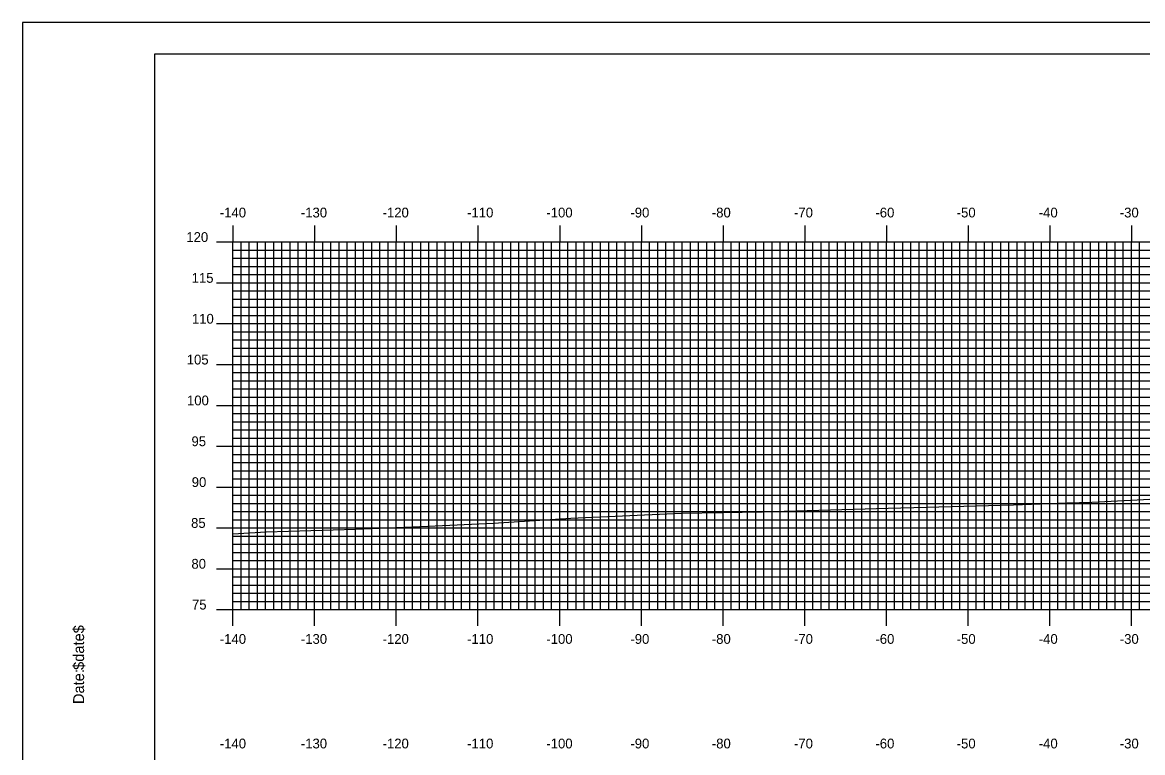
# Model space of a CAD drawing. Extents: x 485 to 829, y -1658 to -1438.
# Drawn here: x 485.3 to 622.5, y -1527.1 to -1437.7 of the extents above; entities that cross this region are included whole.
import ezdxf

# ---------------------------------------------------------------- set-up
doc = ezdxf.new("R2010")
doc.units = 0
for name, color, linetype in [('BORDER', 7, 'Continuous'), ('H_V ANNOTATION', 7, 'Continuous'), ('MAJOR', 7, 'Continuous'), ('MINOR', 7, 'Continuous'), ('PLOT BOUNDARY', 7, 'Continuous'), ('S_Roadway_Centerline', 7, 'Continuous')]:
    doc.layers.add(name, color=color, linetype=linetype)

msp = doc.modelspace()

# ---------------------------------------------------------------- linework, layer by layer
at = {"layer": 'BORDER'}
msp.add_lwpolyline([(501.53, -1651.6), (821.53, -1651.6), (821.53, -1441.6), (501.53, -1441.6)], close=True, dxfattribs=at)
at = {"layer": 'MAJOR'}
for p, q in [((511.13, -1462.6), (511.13, -1464.6)), ((521.13, -1462.6), (521.13, -1464.6)), ((531.13, -1462.6), (531.13, -1464.6)), ((541.13, -1462.6), (541.13, -1464.6)), ((551.13, -1462.6), (551.13, -1464.6)), ((561.13, -1462.6), (561.13, -1464.6)), ((571.13, -1462.6), (571.13, -1464.6)), ((581.13, -1462.6), (581.13, -1464.6)), ((591.13, -1462.6), (591.13, -1464.6)), ((601.13, -1462.6), (601.13, -1464.6)), ((611.13, -1462.6), (611.13, -1464.6)), ((621.13, -1462.6), (621.13, -1464.6)), ((509.13, -1464.6), (511.13, -1464.6)), ((511.13, -1464.6), (791.13, -1464.6)), ((511.13, -1509.6), (511.13, -1464.6)), ((511.13, -1509.6), (511.13, -1464.6)), ((511.13, -1464.6), (791.13, -1464.6)), ((521.13, -1509.6), (521.13, -1464.6)), ((531.13, -1509.6), (531.13, -1464.6)), ((541.13, -1509.6), (541.13, -1464.6)), ((551.13, -1509.6), (551.13, -1464.6)), ((561.13, -1509.6), (561.13, -1464.6)), ((571.13, -1509.6), (571.13, -1464.6)), ((581.13, -1509.6), (581.13, -1464.6)), ((591.13, -1509.6), (591.13, -1464.6)), ((601.13, -1509.6), (601.13, -1464.6)), ((611.13, -1509.6), (611.13, -1464.6)), ((621.13, -1509.6), (621.13, -1464.6)), ((509.13, -1469.6), (511.13, -1469.6)), ((511.13, -1469.6), (791.13, -1469.6)), ((509.13, -1474.6), (511.13, -1474.6)), ((511.13, -1474.6), (791.13, -1474.6)), ((509.13, -1479.6), (511.13, -1479.6)), ((511.13, -1479.6), (791.13, -1479.6)), ((509.13, -1484.6), (511.13, -1484.6)), ((511.13, -1484.6), (791.13, -1484.6)), ((509.13, -1489.6), (511.13, -1489.6)), ((511.13, -1489.6), (791.13, -1489.6)), ((509.13, -1494.6), (511.13, -1494.6)), ((511.13, -1494.6), (791.13, -1494.6)), ((509.13, -1499.6), (511.13, -1499.6)), ((511.13, -1499.6), (791.13, -1499.6)), ((509.13, -1504.6), (511.13, -1504.6)), ((511.13, -1504.6), (791.13, -1504.6)), ((509.13, -1509.6), (511.13, -1509.6)), ((511.13, -1509.6), (791.13, -1509.6)), ((511.13, -1509.6), (791.13, -1509.6)), ((511.13, -1511.61), (511.13, -1509.6)), ((521.13, -1511.61), (521.13, -1509.6)), ((531.13, -1511.61), (531.13, -1509.6)), ((541.13, -1511.61), (541.13, -1509.6)), ((551.13, -1511.61), (551.13, -1509.6)), ((561.13, -1511.61), (561.13, -1509.6)), ((571.13, -1511.61), (571.13, -1509.6)), ((581.13, -1511.61), (581.13, -1509.6)), ((591.13, -1511.61), (591.13, -1509.6)), ((601.13, -1511.61), (601.13, -1509.6)), ((611.13, -1511.61), (611.13, -1509.6)), ((621.13, -1511.61), (621.13, -1509.6))]:
    msp.add_line(p, q, dxfattribs=at)
at = {"layer": 'MINOR'}
for p, q in [((512.13, -1509.6), (512.13, -1464.6)), ((513.13, -1509.6), (513.13, -1464.6)), ((514.13, -1509.6), (514.13, -1464.6)), ((515.13, -1509.6), (515.13, -1464.6)), ((516.13, -1509.6), (516.13, -1464.6)), ((517.13, -1509.6), (517.13, -1464.6)), ((518.13, -1509.6), (518.13, -1464.6)), ((519.13, -1509.6), (519.13, -1464.6)), ((520.13, -1509.6), (520.13, -1464.6)), ((522.13, -1509.6), (522.13, -1464.6)), ((523.13, -1509.6), (523.13, -1464.6)), ((524.13, -1509.6), (524.13, -1464.6)), ((525.13, -1509.6), (525.13, -1464.6)), ((526.13, -1509.6), (526.13, -1464.6)), ((527.13, -1509.6), (527.13, -1464.6)), ((528.13, -1509.6), (528.13, -1464.6)), ((529.13, -1509.6), (529.13, -1464.6)), ((530.13, -1509.6), (530.13, -1464.6)), ((532.13, -1509.6), (532.13, -1464.6)), ((533.13, -1509.6), (533.13, -1464.6)), ((534.13, -1509.6), (534.13, -1464.6)), ((535.13, -1509.6), (535.13, -1464.6)), ((536.13, -1509.6), (536.13, -1464.6)), ((537.13, -1509.6), (537.13, -1464.6)), ((538.13, -1509.6), (538.13, -1464.6)), ((539.13, -1509.6), (539.13, -1464.6)), ((540.13, -1509.6), (540.13, -1464.6)), ((542.13, -1509.6), (542.13, -1464.6)), ((543.13, -1509.6), (543.13, -1464.6)), ((544.13, -1509.6), (544.13, -1464.6)), ((545.13, -1509.6), (545.13, -1464.6)), ((546.13, -1509.6), (546.13, -1464.6)), ((547.13, -1509.6), (547.13, -1464.6)), ((548.13, -1509.6), (548.13, -1464.6)), ((549.13, -1509.6), (549.13, -1464.6)), ((550.13, -1509.6), (550.13, -1464.6)), ((552.13, -1509.6), (552.13, -1464.6)), ((553.13, -1509.6), (553.13, -1464.6)), ((554.13, -1509.6), (554.13, -1464.6)), ((555.13, -1509.6), (555.13, -1464.6)), ((556.13, -1509.6), (556.13, -1464.6)), ((557.13, -1509.6), (557.13, -1464.6)), ((558.13, -1509.6), (558.13, -1464.6)), ((559.13, -1509.6), (559.13, -1464.6)), ((560.13, -1509.6), (560.13, -1464.6)), ((562.13, -1509.6), (562.13, -1464.6)), ((563.13, -1509.6), (563.13, -1464.6)), ((564.13, -1509.6), (564.13, -1464.6)), ((565.13, -1509.6), (565.13, -1464.6)), ((566.13, -1509.6), (566.13, -1464.6)), ((567.13, -1509.6), (567.13, -1464.6)), ((568.13, -1509.6), (568.13, -1464.6)), ((569.13, -1509.6), (569.13, -1464.6)), ((570.13, -1509.6), (570.13, -1464.6)), ((572.13, -1509.6), (572.13, -1464.6)), ((573.13, -1509.6), (573.13, -1464.6)), ((574.13, -1509.6), (574.13, -1464.6)), ((575.13, -1509.6), (575.13, -1464.6)), ((576.13, -1509.6), (576.13, -1464.6)), ((577.13, -1509.6), (577.13, -1464.6)), ((578.13, -1509.6), (578.13, -1464.6)), ((579.13, -1509.6), (579.13, -1464.6)), ((580.13, -1509.6), (580.13, -1464.6)), ((582.13, -1509.6), (582.13, -1464.6)), ((583.13, -1509.6), (583.13, -1464.6)), ((584.13, -1509.6), (584.13, -1464.6)), ((585.13, -1509.6), (585.13, -1464.6)), ((586.13, -1509.6), (586.13, -1464.6)), ((587.13, -1509.6), (587.13, -1464.6)), ((588.13, -1509.6), (588.13, -1464.6)), ((589.13, -1509.6), (589.13, -1464.6)), ((590.13, -1509.6), (590.13, -1464.6)), ((592.13, -1509.6), (592.13, -1464.6)), ((593.13, -1509.6), (593.13, -1464.6)), ((594.13, -1509.6), (594.13, -1464.6)), ((595.13, -1509.6), (595.13, -1464.6)), ((596.13, -1509.6), (596.13, -1464.6)), ((597.13, -1509.6), (597.13, -1464.6)), ((598.13, -1509.6), (598.13, -1464.6)), ((599.13, -1509.6), (599.13, -1464.6)), ((600.13, -1509.6), (600.13, -1464.6)), ((602.13, -1509.6), (602.13, -1464.6)), ((603.13, -1509.6), (603.13, -1464.6)), ((604.13, -1509.6), (604.13, -1464.6)), ((605.13, -1509.6), (605.13, -1464.6)), ((606.13, -1509.6), (606.13, -1464.6)), ((607.13, -1509.6), (607.13, -1464.6)), ((608.13, -1509.6), (608.13, -1464.6)), ((609.13, -1509.6), (609.13, -1464.6)), ((610.13, -1509.6), (610.13, -1464.6)), ((612.13, -1509.6), (612.13, -1464.6)), ((613.13, -1509.6), (613.13, -1464.6)), ((614.13, -1509.6), (614.13, -1464.6)), ((615.13, -1509.6), (615.13, -1464.6)), ((616.13, -1509.6), (616.13, -1464.6)), ((617.13, -1509.6), (617.13, -1464.6)), ((618.13, -1509.6), (618.13, -1464.6)), ((619.13, -1509.6), (619.13, -1464.6)), ((620.13, -1509.6), (620.13, -1464.6)), ((622.13, -1509.6), (622.13, -1464.6)), ((511.13, -1465.6), (791.13, -1465.6)), ((511.13, -1465.6), (513.14, -1465.6)), ((511.13, -1466.6), (791.13, -1466.6)), ((511.13, -1466.6), (513.14, -1466.6)), ((511.13, -1467.6), (791.13, -1467.6)), ((511.13, -1467.6), (513.14, -1467.6)), ((511.13, -1468.6), (791.13, -1468.6)), ((511.13, -1468.6), (513.14, -1468.6)), ((511.13, -1470.6), (791.13, -1470.6)), ((511.13, -1470.6), (513.14, -1470.6)), ((511.13, -1471.6), (791.13, -1471.6)), ((511.13, -1471.6), (513.14, -1471.6)), ((511.13, -1472.6), (791.13, -1472.6)), ((511.13, -1472.6), (513.14, -1472.6)), ((511.13, -1473.6), (791.13, -1473.6)), ((511.13, -1473.6), (513.14, -1473.6)), ((511.13, -1475.6), (791.13, -1475.6)), ((511.13, -1475.6), (513.14, -1475.6)), ((511.13, -1476.6), (791.13, -1476.6)), ((511.13, -1476.6), (513.14, -1476.6)), ((511.13, -1477.6), (791.13, -1477.6)), ((511.13, -1477.6), (513.14, -1477.6)), ((511.13, -1478.6), (791.13, -1478.6)), ((511.13, -1478.6), (513.14, -1478.6)), ((511.13, -1480.6), (791.13, -1480.6)), ((511.13, -1480.6), (513.14, -1480.6)), ((511.13, -1481.6), (791.13, -1481.6)), ((511.13, -1481.6), (513.14, -1481.6)), ((511.13, -1482.6), (791.13, -1482.6)), ((511.13, -1482.6), (513.14, -1482.6)), ((511.13, -1483.6), (791.13, -1483.6)), ((511.13, -1483.6), (513.14, -1483.6)), ((511.13, -1485.6), (791.13, -1485.6)), ((511.13, -1485.6), (513.14, -1485.6)), ((511.13, -1486.6), (791.13, -1486.6)), ((511.13, -1486.6), (513.14, -1486.6)), ((511.13, -1487.6), (791.13, -1487.6)), ((511.13, -1487.6), (513.14, -1487.6)), ((511.13, -1488.6), (791.13, -1488.6)), ((511.13, -1488.6), (513.14, -1488.6)), ((511.13, -1490.6), (791.13, -1490.6)), ((511.13, -1490.6), (513.14, -1490.6)), ((511.13, -1491.6), (791.13, -1491.6)), ((511.13, -1491.6), (513.14, -1491.6)), ((511.13, -1492.6), (791.13, -1492.6)), ((511.13, -1492.6), (513.14, -1492.6)), ((511.13, -1493.6), (791.13, -1493.6)), ((511.13, -1493.6), (513.14, -1493.6)), ((511.13, -1495.6), (791.13, -1495.6)), ((511.13, -1495.6), (513.14, -1495.6)), ((511.13, -1496.6), (791.13, -1496.6)), ((511.13, -1496.6), (513.14, -1496.6)), ((511.13, -1497.6), (791.13, -1497.6)), ((511.13, -1497.6), (513.14, -1497.6)), ((511.13, -1498.6), (791.13, -1498.6)), ((511.13, -1498.6), (513.14, -1498.6)), ((511.13, -1500.6), (791.13, -1500.6)), ((511.13, -1500.6), (513.14, -1500.6)), ((511.13, -1501.6), (791.13, -1501.6)), ((511.13, -1501.6), (513.14, -1501.6)), ((511.13, -1502.6), (791.13, -1502.6)), ((511.13, -1502.6), (513.14, -1502.6)), ((511.13, -1503.6), (791.13, -1503.6)), ((511.13, -1503.6), (513.14, -1503.6)), ((511.13, -1505.6), (791.13, -1505.6)), ((511.13, -1505.6), (513.14, -1505.6)), ((511.13, -1506.6), (791.13, -1506.6)), ((511.13, -1506.6), (513.14, -1506.6)), ((511.13, -1507.6), (791.13, -1507.6)), ((511.13, -1507.6), (513.14, -1507.6)), ((511.13, -1508.6), (791.13, -1508.6)), ((511.13, -1508.6), (513.14, -1508.6))]:
    msp.add_line(p, q, dxfattribs=at)
at = {"layer": 'PLOT BOUNDARY'}
msp.add_lwpolyline([(485.35, -1657.72), (825.35, -1657.72), (825.35, -1437.72), (485.35, -1437.72)], close=True, dxfattribs=at)
at = {"layer": 'S_Roadway_Centerline'}
msp.add_lwpolyline([(511.13, -1500.34), (515.2, -1500.08), (526.15, -1499.77), (535, -1499.39), (543.02, -1499.03), (552.51, -1498.43), (560.63, -1498.06), (566.1, -1497.8), (575.97, -1497.63), (578.6, -1497.57), (591.35, -1497.2), (596.05, -1497.06), (606.71, -1496.77), (613.26, -1496.53), (616.3, -1496.46), (624.98, -1495.99)], dxfattribs=at)

# ---------------------------------------------------------------- texts
at = {"layer": 'BORDER'}
for s, p in [('$date$', (492.9, -1516.99)), ('Date:', (492.9, -1521.17))]:
    msp.add_text(s, height=1.339, rotation=90, dxfattribs=at).set_placement(p)
at = {"layer": 'H_V ANNOTATION'}
for s, p in [('-140', (509.52, -1461.6)), ('-130', (519.44, -1461.6)), ('-120', (529.45, -1461.6)), ('-110', (539.8, -1461.6)), ('-100', (549.5, -1461.6)), ('-90', (559.79, -1461.6)), ('-80', (569.76, -1461.6)), ('-70', (579.82, -1461.6)), ('-60', (589.79, -1461.6)), ('-50', (599.74, -1461.6)), ('-40', (609.79, -1461.6)), ('-30', (619.71, -1461.6)), ('120', (505.42, -1464.6)), ('115', (506.07, -1469.6)), ('110', (506.1, -1474.6)), ('105', (505.47, -1479.6)), ('100', (505.5, -1484.6)), ('95', (506.05, -1489.6)), ('90', (506.08, -1494.6)), ('85', (506, -1499.6)), ('80', (506.04, -1504.6)), ('75', (506.11, -1509.6)), ('-140', (509.52, -1513.8)), ('-130', (519.44, -1513.8)), ('-120', (529.45, -1513.8)), ('-110', (539.8, -1513.8)), ('-100', (549.5, -1513.8)), ('-90', (559.79, -1513.8)), ('-80', (569.76, -1513.8)), ('-70', (579.82, -1513.8)), ('-60', (589.79, -1513.8)), ('-50', (599.74, -1513.8)), ('-40', (609.79, -1513.8)), ('-30', (619.71, -1513.8)), ('-140', (509.52, -1526.6)), ('-130', (519.44, -1526.6)), ('-120', (529.45, -1526.6)), ('-110', (539.8, -1526.6)), ('-100', (549.5, -1526.6)), ('-90', (559.79, -1526.6)), ('-80', (569.76, -1526.6)), ('-70', (579.82, -1526.6)), ('-60', (589.79, -1526.6)), ('-50', (599.74, -1526.6)), ('-40', (609.79, -1526.6)), ('-30', (619.71, -1526.6))]:
    msp.add_text(s, height=1.2, dxfattribs=at).set_placement(p)
at = {"layer": 'MAJOR'}
msp.add_text('-', height=0.012, dxfattribs=at).set_placement((511.13, -1509.6))

doc.saveas('drawing.dxf')
